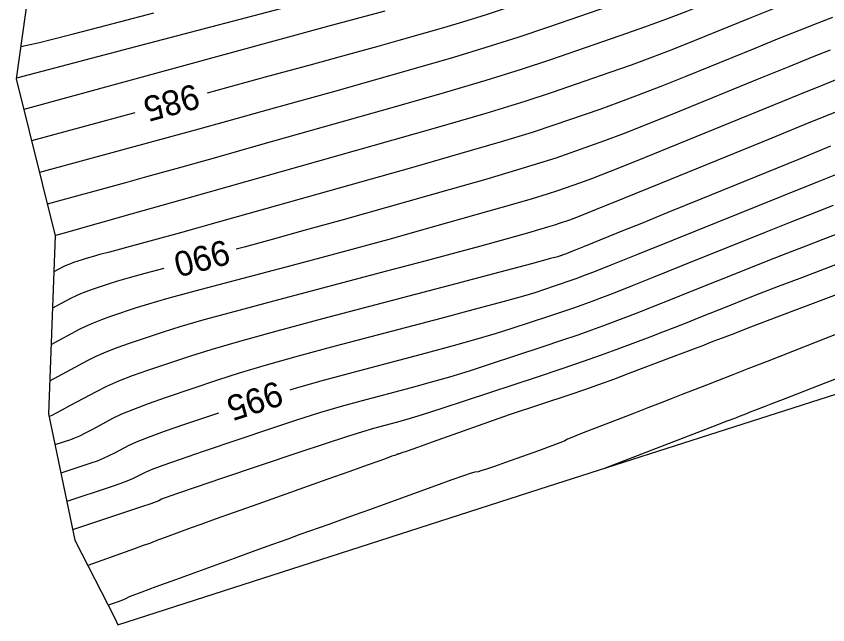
# Model space of a CAD drawing. Extents: x 2175772 to 2185556, y 721391 to 722853.
# Drawn here: x 2178541.3 to 2178632.3, y 721724.1 to 721792.4 of the extents above; entities that cross this region are included whole.
import ezdxf

# ---------------------------------------------------------------- set-up
doc = ezdxf.new("R2010")
doc.units = 0
for name, color, linetype in [('DT_X_Contour_Major', 7, 'Continuous'), ('DT_X_Contour_Minor', 7, 'Continuous'), ('DT_X_TIN_Hull', 7, 'Continuous')]:
    doc.layers.add(name, color=color, linetype=linetype)

msp = doc.modelspace()

# ---------------------------------------------------------------- linework, layer by layer
at = {"layer": 'DT_X_Contour_Major'}
for points in [[(2178635.464, 721807.413), (2178628.106, 721804.676), (2178625.625, 721803.751), (2178623.7, 721803.028), (2178622.332, 721802.507), (2178621.52, 721802.188), (2178620.096, 721801.607), (2178619.14, 721801.247), (2178617.339, 721800.602), (2178614.692, 721799.673), (2178611.2, 721798.46), (2178600.761, 721794.845), (2178597.101, 721793.592), (2178593.95, 721792.546), (2178591.308, 721791.706), (2178589.175, 721791.072), (2178584.165, 721789.657), (2178581.82, 721789.001), (2178578.542, 721788.095), (2178574.331, 721786.939), (2178569.187, 721785.532), (2178562.677, 721783.755)], [(2178632.542, 721788.572), (2178630.52, 721787.772), (2178627.91, 721786.723), (2178624.711, 721785.423), (2178615.398, 721781.623), (2178612.164, 721780.315), (2178609.447, 721779.239), (2178607.247, 721778.396), (2178605.563, 721777.787), (2178601.763, 721776.47), (2178599.954, 721775.88), (2178597.377, 721775.095), (2178594.031, 721774.116), (2178589.917, 721772.942), (2178577.923, 721769.554), (2178573.691, 721768.364), (2178569.991, 721767.335), (2178566.824, 721766.468), (2178565.944, 721766.232)], [(2178554.574, 721781.543), (2178543.004, 721778.385)], [(2178632.884, 721771.163), (2178630.893, 721770.378), (2178628.312, 721769.349), (2178625.141, 721768.077), (2178615.898, 721764.36), (2178612.773, 721763.105), (2178610.329, 721762.129), (2178608.567, 721761.431), (2178607.487, 721761.012), (2178605.515, 721760.266), (2178604.675, 721759.957), (2178603.636, 721759.591), (2178602.397, 721759.169), (2178600.958, 721758.688), (2178596.856, 721757.332), (2178595.1, 721756.779), (2178592.909, 721756.136), (2178590.283, 721755.405), (2178587.222, 721754.584), (2178578.481, 721752.277), (2178575.297, 721751.413), (2178572.302, 721750.553), (2178571.951, 721750.446)], [(2178557.824, 721764.082), (2178555.709, 721763.517), (2178553.959, 721763.035), (2178552.621, 721762.649), (2178551.695, 721762.358), (2178549.776, 721761.71), (2178549.09, 721761.467), (2178548.472, 721761.224), (2178547.92, 721760.982), (2178547.435, 721760.74), (2178545.329, 721759.61)], [(2178640.192, 721754.38), (2178632.048, 721751.237), (2178627.263, 721749.39), (2178625.863, 721748.848), (2178625.124, 721748.561), (2178624.035, 721748.135), (2178623.654, 721747.986), (2178623.058, 721747.752), (2178622.842, 721747.668), (2178622.34, 721747.472), (2178621.901, 721747.302), (2178620.959, 721746.939), (2178619.514, 721746.383), (2178617.566, 721745.634), (2178607.303, 721741.688)], [(2178563.96, 721747.856), (2178560.151, 721746.57), (2178557.868, 721745.784), (2178556.065, 721745.13), (2178554.742, 721744.608), (2178553.9, 721744.219), (2178552.292, 721743.356), (2178551.674, 721743.043), (2178551.027, 721742.751), (2178550.349, 721742.479), (2178549.643, 721742.228), (2178546.275, 721741.106)]]:
    msp.add_lwpolyline(points, dxfattribs=at)
at = {"layer": 'DT_X_Contour_Minor'}
for points in [[(2178635.774, 721803.981), (2178629.28, 721801.565), (2178627.008, 721800.715), (2178625.064, 721799.977), (2178623.447, 721799.35), (2178622.158, 721798.835), (2178619.157, 721797.61), (2178617.745, 721797.061), (2178615.76, 721796.33), (2178613.203, 721795.418), (2178610.073, 721794.325), (2178600.962, 721791.17), (2178597.498, 721790.001), (2178593.94, 721788.859), (2178590.288, 721787.746), (2178586.541, 721786.66), (2178576.424, 721783.802), (2178572.637, 721782.737), (2178568.862, 721781.684), (2178565.1, 721780.643), (2178561.35, 721779.615), (2178543.88, 721774.846)], [(2178636.084, 721800.548), (2178630.454, 721798.454), (2178628.391, 721797.679), (2178626.428, 721796.925), (2178624.563, 721796.193), (2178622.796, 721795.482), (2178618.217, 721793.614), (2178616.35, 721792.874), (2178614.182, 721792.057), (2178611.714, 721791.163), (2178608.945, 721790.191), (2178601.162, 721787.495), (2178597.895, 721786.409), (2178593.93, 721785.172), (2178589.267, 721783.785), (2178583.907, 721782.248), (2178568.684, 721777.948), (2178563.454, 721776.472), (2178559.182, 721775.272), (2178555.868, 721774.348), (2178553.513, 721773.698), (2178544.756, 721771.307)], [(2178636.394, 721797.116), (2178631.627, 721795.343), (2178629.775, 721794.643), (2178627.792, 721793.874), (2178625.678, 721793.036), (2178623.435, 721792.129), (2178617.277, 721789.617), (2178614.955, 721788.688), (2178612.604, 721787.785), (2178610.225, 721786.907), (2178607.818, 721786.056), (2178601.363, 721783.82), (2178598.291, 721782.817), (2178593.919, 721781.486), (2178588.247, 721779.825), (2178581.273, 721777.836), (2178560.943, 721772.093), (2178554.271, 721770.208), (2178546.637, 721768.052), (2178545.676, 721767.781), (2178545.633, 721767.769)], [(2178541.296, 721785.462), (2178541.364, 721785.476), (2178555.406, 721789.164), (2178574.091, 721794.074)], [(2178541.792, 721788.999), (2178543.896, 721789.441), (2178545.036, 721789.72), (2178547.552, 721790.366), (2178551.444, 721791.38), (2178556.714, 721792.762)], [(2178582.592, 721792.969), (2178576.189, 721791.221), (2178542.127, 721781.923)], [(2178632.801, 721792.232), (2178631.158, 721791.608), (2178629.156, 721790.823), (2178626.794, 721789.88), (2178624.073, 721788.776), (2178616.338, 721785.62), (2178613.559, 721784.501), (2178611.025, 721783.512), (2178608.736, 721782.652), (2178606.691, 721781.921), (2178601.563, 721780.145), (2178599.122, 721779.348), (2178595.644, 721778.289), (2178591.129, 721776.968), (2178585.578, 721775.384), (2178569.392, 721770.812), (2178563.933, 721769.273), (2178559.697, 721768.084), (2178556.682, 721767.246), (2178554.89, 721766.759), (2178551.739, 721765.927), (2178550.661, 721765.639), (2178549.788, 721765.399), (2178549.12, 721765.206), (2178548.659, 721765.061), (2178547.702, 721764.738), (2178547.359, 721764.617), (2178547.051, 721764.496), (2178546.775, 721764.375), (2178546.534, 721764.254), (2178545.483, 721763.691)], [(2178633.925, 721785.536), (2178631.884, 721784.721), (2178629.025, 721783.566), (2178625.35, 721782.07), (2178614.459, 721777.627), (2178610.769, 721776.128), (2178607.869, 721774.967), (2178605.758, 721774.141), (2178604.436, 721773.652), (2178601.964, 721772.796), (2178600.787, 721772.411), (2178599.11, 721771.901), (2178596.933, 721771.264), (2178594.257, 721770.5), (2178586.453, 721768.296), (2178583.448, 721767.455), (2178580.285, 721766.586), (2178576.965, 721765.69), (2178573.488, 721764.765), (2178564.005, 721762.262), (2178560.758, 721761.395), (2178558.13, 721760.672), (2178556.122, 721760.091), (2178554.732, 721759.655), (2178551.851, 721758.682), (2178550.822, 721758.317), (2178549.892, 721757.953), (2178549.064, 721757.589), (2178548.336, 721757.225), (2178545.174, 721755.53)], [(2178633.247, 721781.67), (2178630.141, 721780.409), (2178625.988, 721778.717), (2178613.519, 721773.63), (2178609.374, 721771.942), (2178606.29, 721770.694), (2178604.269, 721769.886), (2178603.309, 721769.517), (2178602.164, 721769.121), (2178601.619, 721768.943), (2178600.843, 721768.706), (2178599.835, 721768.411), (2178598.596, 721768.058), (2178594.984, 721767.038), (2178593.205, 721766.546), (2178590.58, 721765.837), (2178587.107, 721764.911), (2178582.787, 721763.768), (2178570.138, 721760.429), (2178565.807, 721759.273), (2178562.302, 721758.308), (2178559.622, 721757.534), (2178557.769, 721756.952), (2178553.926, 721755.654), (2178552.553, 721755.168), (2178551.313, 721754.682), (2178550.208, 721754.196), (2178549.237, 721753.711), (2178545.02, 721751.449)], [(2178632.575, 721777.791), (2178628.971, 721776.321), (2178618.051, 721771.866), (2178614.335, 721770.35), (2178611.377, 721769.146), (2178609.176, 721768.252), (2178607.732, 721767.668), (2178604.894, 721766.526), (2178603.956, 721766.15), (2178603.273, 721765.875), (2178602.844, 721765.703), (2178602.669, 721765.634), (2178602.542, 721765.586), (2178602.488, 721765.566), (2178602.421, 721765.542), (2178602.341, 721765.515), (2178602.248, 721765.484), (2178601.983, 721765.397), (2178601.196, 721765.183), (2178599.031, 721764.607), (2178595.49, 721763.67), (2178590.572, 721762.371), (2178575.621, 721758.425), (2178570.49, 721757.054), (2178566.311, 721755.901), (2178563.083, 721754.966), (2178560.805, 721754.249), (2178556.001, 721752.626), (2178554.289, 721752.021), (2178552.756, 721751.422), (2178551.403, 721750.83), (2178550.228, 721750.245), (2178547.334, 721748.693), (2178546.381, 721748.182), (2178545.69, 721747.814), (2178545.263, 721747.589), (2178545.098, 721747.507), (2178544.944, 721747.455)], [(2178634.052, 721774.953), (2178631.079, 721773.76), (2178627.06, 721772.145), (2178614.949, 721767.274), (2178610.926, 721765.657), (2178607.939, 721764.46), (2178605.99, 721763.682), (2178605.078, 721763.323), (2178604.028, 721762.926), (2178603.582, 721762.762), (2178603.028, 721762.567), (2178602.369, 721762.342), (2178601.603, 721762.086), (2178599.419, 721761.364), (2178598.148, 721760.981), (2178595.97, 721760.372), (2178592.886, 721759.538), (2178588.897, 721758.478), (2178577.051, 721755.351), (2178572.894, 721754.234), (2178569.307, 721753.227), (2178566.289, 721752.331), (2178563.842, 721751.545), (2178558.076, 721749.598), (2178556.079, 721748.902), (2178554.411, 721748.276), (2178553.073, 721747.719), (2178552.064, 721747.232), (2178549.813, 721746.025), (2178549.027, 721745.613), (2178548.358, 721745.283), (2178547.806, 721745.034), (2178547.37, 721744.868), (2178545.609, 721744.28)], [(2178636.646, 721769.214), (2178631.707, 721767.338), (2178629.788, 721766.603), (2178627.734, 721765.803), (2178625.545, 721764.938), (2178623.222, 721764.009), (2178616.847, 721761.445), (2178614.62, 721760.553), (2178612.719, 721759.798), (2178611.144, 721759.18), (2178609.895, 721758.701), (2178607.001, 721757.605), (2178605.769, 721757.153), (2178604.244, 721756.616), (2178602.425, 721755.995), (2178600.314, 721755.291), (2178594.292, 721753.3), (2178592.052, 721752.577), (2178589.848, 721751.901), (2178587.68, 721751.272), (2178585.548, 721750.691), (2178579.91, 721749.203), (2178577.7, 721748.593), (2178575.298, 721747.879), (2178572.703, 721747.061), (2178569.915, 721746.139), (2178562.226, 721743.542), (2178559.658, 721742.665), (2178557.72, 721741.984), (2178556.412, 721741.497), (2178555.735, 721741.206), (2178554.77, 721740.688), (2178554.321, 721740.474), (2178553.695, 721740.219), (2178552.893, 721739.925), (2178551.915, 721739.589), (2178546.94, 721737.931)], [(2178636.058, 721765.603), (2178629.13, 721762.972), (2178626.692, 721762.043), (2178624.575, 721761.228), (2178622.778, 721760.527), (2178621.303, 721759.941), (2178617.797, 721758.531), (2178616.467, 721758), (2178615.109, 721757.467), (2178613.721, 721756.93), (2178612.304, 721756.39), (2178608.487, 721754.945), (2178606.862, 721754.348), (2178604.851, 721753.64), (2178602.453, 721752.822), (2178599.669, 721751.893), (2178591.728, 721749.267), (2178589.004, 721748.375), (2178586.786, 721747.665), (2178585.076, 721747.14), (2178583.873, 721746.797), (2178581.34, 721746.129), (2178580.104, 721745.772), (2178578.293, 721745.205), (2178575.91, 721744.426), (2178572.952, 721743.436), (2178564.301, 721740.514), (2178561.447, 721739.547), (2178559.374, 721738.838), (2178558.082, 721738.386), (2178557.571, 721738.193), (2178557.249, 721738.02), (2178556.967, 721737.905), (2178556.363, 721737.688), (2178555.436, 721737.37), (2178554.187, 721736.95), (2178547.606, 721734.756)], [(2178635.471, 721761.992), (2178626.552, 721758.605), (2178623.596, 721757.482), (2178621.416, 721756.653), (2178620.012, 721756.116), (2178619.384, 721755.873), (2178618.746, 721755.617), (2178618.314, 721755.448), (2178617.498, 721755.136), (2178616.298, 721754.679), (2178614.713, 721754.079), (2178609.973, 721752.285), (2178608.233, 721751.635), (2178606.567, 721751.031), (2178604.974, 721750.473), (2178603.455, 721749.96), (2178596.54, 721747.674), (2178587.9, 721744.586), (2178586.277, 721744.007), (2178585.111, 721743.592), (2178584.402, 721743.342), (2178584.15, 721743.257), (2178584.089, 721743.248), (2178584.029, 721743.231), (2178583.895, 721743.185), (2178583.688, 721743.112), (2178583.406, 721743.01), (2178582.557, 721742.702), (2178581.915, 721742.472), (2178580.626, 721742.012), (2178578.69, 721741.322), (2178576.107, 721740.402), (2178568.356, 721737.644), (2178565.71, 721736.702), (2178563.584, 721735.943), (2178561.98, 721735.368), (2178560.896, 721734.976), (2178557.973, 721733.913), (2178557.443, 721733.717), (2178557.109, 721733.592), (2178556.971, 721733.535), (2178556.863, 721733.477), (2178556.687, 721733.408), (2178556.241, 721733.243), (2178555.526, 721732.984), (2178554.54, 721732.63), (2178549.309, 721730.757)], [(2178633.811, 721756.921), (2178625.457, 721753.653), (2178623.295, 721752.807), (2178621.446, 721752.084), (2178619.909, 721751.483), (2178618.685, 721751.004), (2178615.838, 721749.89), (2178614.708, 721749.449), (2178613.455, 721748.963), (2178612.079, 721748.431), (2178610.579, 721747.853), (2178606.413, 721746.252), (2178605.033, 721745.718), (2178604.017, 721745.318), (2178603.365, 721745.052), (2178603.076, 721744.919), (2178602.791, 721744.743), (2178602.525, 721744.623), (2178601.94, 721744.397), (2178601.037, 721744.064), (2178599.816, 721743.624), (2178596.134, 721742.308), (2178594.907, 721741.874), (2178593.989, 721741.558), (2178593.379, 721741.36), (2178593.076, 721741.28), (2178592.681, 721741.225), (2178592.296, 721741.114), (2178591.435, 721740.822), (2178590.1, 721740.35), (2178588.29, 721739.697), (2178582.831, 721737.716), (2178580.889, 721737.012), (2178579.155, 721736.386), (2178577.63, 721735.837), (2178576.314, 721735.367), (2178573.083, 721734.217), (2178571.713, 721733.728), (2178570.029, 721733.121), (2178568.028, 721732.397), (2178565.713, 721731.556), (2178559.118, 721729.158), (2178556.939, 721728.363), (2178555.347, 721727.776), (2178554.344, 721727.398), (2178553.928, 721727.228), (2178553.603, 721727.053), (2178553.463, 721726.984), (2178553.288, 721726.908), (2178553.077, 721726.824), (2178552.831, 721726.733), (2178551.6, 721726.292)]]:
    msp.add_lwpolyline(points, dxfattribs=at)
at = {"layer": 'DT_X_TIN_Hull'}
msp.add_lwpolyline([(2178645.272, 721972.998), (2178625.76, 721928.988), (2178601.171, 721874.174), (2178550.61, 721851.86), (2178541.28, 721785.345), (2178545.637, 721767.751), (2178544.88, 721747.76), (2178547.846, 721733.61), (2178552.305, 721724.917), (2178552.665, 721724.106), (2178576.461, 721731.768), (2178599.926, 721739.323), (2178623.731, 721746.955), (2178647.535, 721754.586)], dxfattribs=at)

# ---------------------------------------------------------------- texts
at = {"layer": 'DT_X_Contour_Major'}
for s, rotation, p in [('985', 195.26879, (2178561.351, 721784.844)), ('990', 194.83272, (2178564.766, 721767.365)), ('995', 197.95408, (2178570.584, 721751.517))]:
    msp.add_text(s, height=2.8, rotation=rotation, dxfattribs=at).set_placement(p)

doc.saveas('drawing.dxf')
